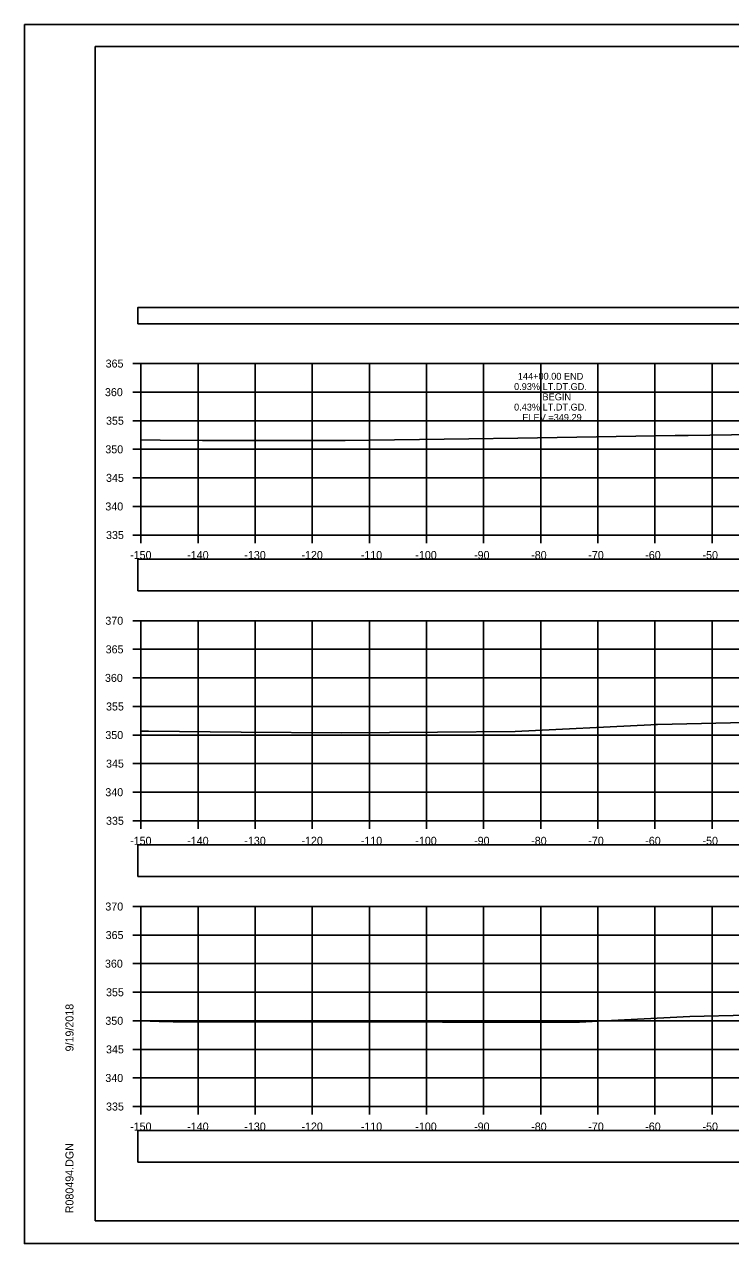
# Model space of a CAD drawing. Extents: x 1376273 to 1384221, y 378927 to 384592.
# Drawn here: x 1376887.4 to 1377011, y 382458.6 to 382671.9 of the extents above; entities that cross this region are included whole.
import ezdxf

# ---------------------------------------------------------------- set-up
doc = ezdxf.new("R2010")
doc.units = 0
for name, color, linetype in [('R_Axis', 7, 'Continuous'), ('R_Axis Annot', 7, 'Continuous'), ('R_Border', 7, 'Continuous'), ('R_Exist Surface', 7, 'Continuous'), ('R_Grid', 7, 'Continuous'), ('R_No Plot', 7, 'Continuous'), ('R_Xsect Elev', 7, 'Continuous')]:
    doc.layers.add(name, color=color, linetype=linetype)

msp = doc.modelspace()

# ---------------------------------------------------------------- linework, layer by layer
at = {"layer": 'R_Axis'}
for p, q in [((1376906.37, 382612.54), (1376907.77, 382612.54)), ((1376907.77, 382582.54), (1376907.77, 382612.54)), ((1376906.37, 382607.54), (1376907.77, 382607.54)), ((1376906.37, 382602.54), (1376907.77, 382602.54)), ((1376906.37, 382597.54), (1376907.77, 382597.54)), ((1376906.37, 382592.54), (1376907.77, 382592.54)), ((1376906.37, 382587.54), (1376907.77, 382587.54)), ((1376906.37, 382582.54), (1376907.77, 382582.54)), ((1376907.77, 382582.54), (1377207.77, 382582.54)), ((1376907.77, 382581.14), (1376907.77, 382582.54)), ((1376917.77, 382581.14), (1376917.77, 382582.54)), ((1376927.77, 382581.14), (1376927.77, 382582.54)), ((1376937.77, 382581.14), (1376937.77, 382582.54)), ((1376947.77, 382581.14), (1376947.77, 382582.54)), ((1376957.77, 382581.14), (1376957.77, 382582.54)), ((1376967.77, 382581.14), (1376967.77, 382582.54)), ((1376977.77, 382581.14), (1376977.77, 382582.54)), ((1376987.77, 382581.14), (1376987.77, 382582.54)), ((1376997.77, 382581.14), (1376997.77, 382582.54)), ((1377007.77, 382581.14), (1377007.77, 382582.54)), ((1376906.37, 382567.54), (1376907.77, 382567.54)), ((1376907.77, 382532.54), (1376907.77, 382567.54)), ((1376906.37, 382562.54), (1376907.77, 382562.54)), ((1376906.37, 382557.54), (1376907.77, 382557.54)), ((1376906.37, 382552.54), (1376907.77, 382552.54)), ((1376906.37, 382547.54), (1376907.77, 382547.54)), ((1376906.37, 382542.54), (1376907.77, 382542.54)), ((1376906.37, 382537.54), (1376907.77, 382537.54)), ((1376906.37, 382532.54), (1376907.77, 382532.54)), ((1376907.77, 382532.54), (1377207.77, 382532.54)), ((1376907.77, 382531.14), (1376907.77, 382532.54)), ((1376917.77, 382531.14), (1376917.77, 382532.54)), ((1376927.77, 382531.14), (1376927.77, 382532.54)), ((1376937.77, 382531.14), (1376937.77, 382532.54)), ((1376947.77, 382531.14), (1376947.77, 382532.54)), ((1376957.77, 382531.14), (1376957.77, 382532.54)), ((1376967.77, 382531.14), (1376967.77, 382532.54)), ((1376977.77, 382531.14), (1376977.77, 382532.54)), ((1376987.77, 382531.14), (1376987.77, 382532.54)), ((1376997.77, 382531.14), (1376997.77, 382532.54)), ((1377007.77, 382531.14), (1377007.77, 382532.54)), ((1376906.37, 382517.54), (1376907.77, 382517.54)), ((1376907.77, 382482.54), (1376907.77, 382517.54)), ((1376906.37, 382512.54), (1376907.77, 382512.54)), ((1376906.37, 382507.54), (1376907.77, 382507.54)), ((1376906.37, 382502.54), (1376907.77, 382502.54)), ((1376906.37, 382497.54), (1376907.77, 382497.54)), ((1376906.37, 382492.54), (1376907.77, 382492.54)), ((1376906.37, 382487.54), (1376907.77, 382487.54)), ((1376906.37, 382482.54), (1376907.77, 382482.54)), ((1376907.77, 382482.54), (1377207.77, 382482.54)), ((1376907.77, 382481.14), (1376907.77, 382482.54)), ((1376917.77, 382481.14), (1376917.77, 382482.54)), ((1376927.77, 382481.14), (1376927.77, 382482.54)), ((1376937.77, 382481.14), (1376937.77, 382482.54)), ((1376947.77, 382481.14), (1376947.77, 382482.54)), ((1376957.77, 382481.14), (1376957.77, 382482.54)), ((1376967.77, 382481.14), (1376967.77, 382482.54)), ((1376977.77, 382481.14), (1376977.77, 382482.54)), ((1376987.77, 382481.14), (1376987.77, 382482.54)), ((1376997.77, 382481.14), (1376997.77, 382482.54)), ((1377007.77, 382481.14), (1377007.77, 382482.54))]:
    msp.add_line(p, q, dxfattribs=at)
at = {"layer": 'R_Axis Annot'}
for points in [[(1376907.2, 382619.52), (1377209.01, 382619.52), (1377209.01, 382622.34), (1376907.2, 382622.34)], [(1376907.2, 382572.79), (1377209.01, 382572.79), (1377209.01, 382578.31), (1376907.2, 382578.31)], [(1376907.2, 382522.8), (1377209.01, 382522.8), (1377209.01, 382528.32), (1376907.2, 382528.32)], [(1376907.2, 382472.82), (1377209.01, 382472.82), (1377209.01, 382478.34), (1376907.2, 382478.34)]]:
    msp.add_lwpolyline(points, close=True, dxfattribs=at)
at = {"layer": 'R_Border'}
for p, q in [((1376899.77, 382668), (1377215.95, 382668)), ((1376899.77, 382462.54), (1376899.77, 382668)), ((1376899.77, 382462.54), (1376899.77, 382462.54)), ((1377215.95, 382462.54), (1376899.77, 382462.54))]:
    msp.add_line(p, q, dxfattribs=at)
at = {"layer": 'R_Exist Surface'}
for points in [[(1376907.77, 382599.2), (1376911.14, 382599.15), (1376918.54, 382599.1), (1376943.54, 382599.06), (1376965.19, 382599.35), (1376973.75, 382599.48), (1377001.33, 382599.96), (1377002.2, 382599.96), (1377003.6, 382599.98), (1377018.79, 382600.2)], [(1376907.77, 382548.23), (1376909.11, 382548.2), (1376925.31, 382548.07), (1376942.89, 382547.92), (1376959.72, 382548.03), (1376973.29, 382548.15), (1376997.05, 382549.34), (1376997.8, 382549.38), (1376998.24, 382549.39), (1377016.17, 382549.82)], [(1376907.77, 382497.53), (1376910.96, 382497.44), (1376913.44, 382497.34), (1376925.87, 382497.35), (1376949.75, 382497.34), (1376960.58, 382497.32), (1376984.54, 382497.3), (1376987.91, 382497.47), (1377003.86, 382498.29), (1377013.99, 382498.5)]]:
    msp.add_lwpolyline(points, dxfattribs=at)
at = {"layer": 'R_Grid'}
for p, q in [((1376907.77, 382612.54), (1377207.77, 382612.54)), ((1376907.77, 382582.54), (1376907.77, 382612.54)), ((1376907.77, 382612.54), (1377207.77, 382612.54)), ((1376907.77, 382582.54), (1376907.77, 382612.54)), ((1376917.77, 382582.54), (1376917.77, 382612.54)), ((1376917.77, 382582.54), (1376917.77, 382612.54)), ((1376927.77, 382582.54), (1376927.77, 382612.54)), ((1376927.77, 382582.54), (1376927.77, 382612.54)), ((1376937.77, 382582.54), (1376937.77, 382612.54)), ((1376937.77, 382582.54), (1376937.77, 382612.54)), ((1376947.77, 382582.54), (1376947.77, 382612.54)), ((1376947.77, 382582.54), (1376947.77, 382612.54)), ((1376957.77, 382582.54), (1376957.77, 382612.54)), ((1376957.77, 382582.54), (1376957.77, 382612.54)), ((1376967.77, 382582.54), (1376967.77, 382612.54)), ((1376967.77, 382582.54), (1376967.77, 382612.54)), ((1376977.77, 382582.54), (1376977.77, 382612.54)), ((1376977.77, 382582.54), (1376977.77, 382612.54)), ((1376987.77, 382582.54), (1376987.77, 382612.54)), ((1376987.77, 382582.54), (1376987.77, 382612.54)), ((1376997.77, 382582.54), (1376997.77, 382612.54)), ((1376997.77, 382582.54), (1376997.77, 382612.54)), ((1377007.77, 382582.54), (1377007.77, 382612.54)), ((1377007.77, 382582.54), (1377007.77, 382612.54)), ((1376907.77, 382607.54), (1377207.77, 382607.54)), ((1376907.77, 382607.54), (1377207.77, 382607.54)), ((1376907.77, 382602.54), (1377207.77, 382602.54)), ((1376907.77, 382602.54), (1377207.77, 382602.54)), ((1376907.77, 382597.54), (1377207.77, 382597.54)), ((1376907.77, 382597.54), (1377207.77, 382597.54)), ((1376907.77, 382592.54), (1377207.77, 382592.54)), ((1376907.77, 382592.54), (1377207.77, 382592.54)), ((1376907.77, 382587.54), (1377207.77, 382587.54)), ((1376907.77, 382587.54), (1377207.77, 382587.54)), ((1376907.77, 382582.54), (1377207.77, 382582.54)), ((1376907.77, 382582.54), (1377207.77, 382582.54)), ((1376907.77, 382567.54), (1377207.77, 382567.54)), ((1376907.77, 382532.54), (1376907.77, 382567.54)), ((1376907.77, 382567.54), (1377207.77, 382567.54)), ((1376907.77, 382532.54), (1376907.77, 382567.54)), ((1376917.77, 382532.54), (1376917.77, 382567.54)), ((1376917.77, 382532.54), (1376917.77, 382567.54)), ((1376927.77, 382532.54), (1376927.77, 382567.54)), ((1376927.77, 382532.54), (1376927.77, 382567.54)), ((1376937.77, 382532.54), (1376937.77, 382567.54)), ((1376937.77, 382532.54), (1376937.77, 382567.54)), ((1376947.77, 382532.54), (1376947.77, 382567.54)), ((1376947.77, 382532.54), (1376947.77, 382567.54)), ((1376957.77, 382532.54), (1376957.77, 382567.54)), ((1376957.77, 382532.54), (1376957.77, 382567.54)), ((1376967.77, 382532.54), (1376967.77, 382567.54)), ((1376967.77, 382532.54), (1376967.77, 382567.54)), ((1376977.77, 382532.54), (1376977.77, 382567.54)), ((1376977.77, 382532.54), (1376977.77, 382567.54)), ((1376987.77, 382532.54), (1376987.77, 382567.54)), ((1376987.77, 382532.54), (1376987.77, 382567.54)), ((1376997.77, 382532.54), (1376997.77, 382567.54)), ((1376997.77, 382532.54), (1376997.77, 382567.54)), ((1377007.77, 382532.54), (1377007.77, 382567.54)), ((1377007.77, 382532.54), (1377007.77, 382567.54)), ((1376907.77, 382562.54), (1377207.77, 382562.54)), ((1376907.77, 382562.54), (1377207.77, 382562.54)), ((1376907.77, 382557.54), (1377207.77, 382557.54)), ((1376907.77, 382557.54), (1377207.77, 382557.54)), ((1376907.77, 382552.54), (1377207.77, 382552.54)), ((1376907.77, 382552.54), (1377207.77, 382552.54)), ((1376907.77, 382547.54), (1377207.77, 382547.54)), ((1376907.77, 382547.54), (1377207.77, 382547.54)), ((1376907.77, 382542.54), (1377207.77, 382542.54)), ((1376907.77, 382542.54), (1377207.77, 382542.54)), ((1376907.77, 382537.54), (1377207.77, 382537.54)), ((1376907.77, 382537.54), (1377207.77, 382537.54)), ((1376907.77, 382532.54), (1377207.77, 382532.54)), ((1376907.77, 382532.54), (1377207.77, 382532.54)), ((1376907.77, 382517.54), (1377207.77, 382517.54)), ((1376907.77, 382482.54), (1376907.77, 382517.54)), ((1376907.77, 382517.54), (1377207.77, 382517.54)), ((1376907.77, 382482.54), (1376907.77, 382517.54)), ((1376917.77, 382482.54), (1376917.77, 382517.54)), ((1376917.77, 382482.54), (1376917.77, 382517.54)), ((1376927.77, 382482.54), (1376927.77, 382517.54)), ((1376927.77, 382482.54), (1376927.77, 382517.54)), ((1376937.77, 382482.54), (1376937.77, 382517.54)), ((1376937.77, 382482.54), (1376937.77, 382517.54)), ((1376947.77, 382482.54), (1376947.77, 382517.54)), ((1376947.77, 382482.54), (1376947.77, 382517.54)), ((1376957.77, 382482.54), (1376957.77, 382517.54)), ((1376957.77, 382482.54), (1376957.77, 382517.54)), ((1376967.77, 382482.54), (1376967.77, 382517.54)), ((1376967.77, 382482.54), (1376967.77, 382517.54)), ((1376977.77, 382482.54), (1376977.77, 382517.54)), ((1376977.77, 382482.54), (1376977.77, 382517.54)), ((1376987.77, 382482.54), (1376987.77, 382517.54)), ((1376987.77, 382482.54), (1376987.77, 382517.54)), ((1376997.77, 382482.54), (1376997.77, 382517.54)), ((1376997.77, 382482.54), (1376997.77, 382517.54)), ((1377007.77, 382482.54), (1377007.77, 382517.54)), ((1377007.77, 382482.54), (1377007.77, 382517.54)), ((1376907.77, 382512.54), (1377207.77, 382512.54)), ((1376907.77, 382512.54), (1377207.77, 382512.54)), ((1376907.77, 382507.54), (1377207.77, 382507.54)), ((1376907.77, 382507.54), (1377207.77, 382507.54)), ((1376907.77, 382502.54), (1377207.77, 382502.54)), ((1376907.77, 382502.54), (1377207.77, 382502.54)), ((1376907.77, 382497.54), (1377207.77, 382497.54)), ((1376907.77, 382497.54), (1377207.77, 382497.54)), ((1376907.77, 382492.54), (1377207.77, 382492.54)), ((1376907.77, 382492.54), (1377207.77, 382492.54)), ((1376907.77, 382487.54), (1377207.77, 382487.54)), ((1376907.77, 382487.54), (1377207.77, 382487.54)), ((1376907.77, 382482.54), (1377207.77, 382482.54)), ((1376907.77, 382482.54), (1377207.77, 382482.54))]:
    msp.add_line(p, q, dxfattribs=at)
at = {"layer": 'R_No Plot'}
for p, q in [((1376887.37, 382671.89), (1377220.7, 382671.89)), ((1376887.37, 382458.56), (1377220.7, 382458.56))]:
    msp.add_line(p, q, dxfattribs=at)
for points in [[(1376887.36, 382671.89), (1377220.7, 382671.89), (1377220.7, 382458.55), (1376887.36, 382458.55)], [(1377133.69, 382668), (1377133.69, 382658.12), (1377169.42, 382658.12), (1377169.42, 382655.2), (1377192.62, 382655.2), (1377192.62, 382630.86), (1377215.95, 382630.86), (1377215.95, 382462.54), (1376899.77, 382462.54), (1376899.77, 382668)]]:
    msp.add_lwpolyline(points, close=True, dxfattribs=at)

# ---------------------------------------------------------------- texts
at = {"layer": 'R_Axis Annot'}
for s, p in [('365', (1376901.59, 382611.84)), ('360', (1376901.47, 382606.84)), ('355', (1376901.66, 382601.84)), ('350', (1376901.54, 382596.84)), ('345', (1376901.66, 382591.84)), ('340', (1376901.54, 382586.84)), ('335', (1376901.66, 382581.84)), ('-150', (1376905.88, 382578.34)), ('-140', (1376915.88, 382578.34)), ('-130', (1376925.88, 382578.34)), ('-120', (1376935.88, 382578.34)), ('-110', (1376946.27, 382578.34)), ('-100', (1376955.82, 382578.34)), ('-90', (1376966.11, 382578.34)), ('-80', (1376976.11, 382578.34)), ('-70', (1376986.11, 382578.34)), ('-60', (1376996.08, 382578.34)), ('-50', (1377006.11, 382578.34)), ('370', (1376901.54, 382566.84)), ('365', (1376901.59, 382561.84)), ('360', (1376901.47, 382556.84)), ('355', (1376901.66, 382551.84)), ('350', (1376901.54, 382546.84)), ('345', (1376901.66, 382541.84)), ('340', (1376901.54, 382536.84)), ('335', (1376901.66, 382531.84)), ('-150', (1376905.88, 382528.34)), ('-140', (1376915.88, 382528.34)), ('-130', (1376925.88, 382528.34)), ('-120', (1376935.88, 382528.34)), ('-110', (1376946.27, 382528.34)), ('-100', (1376955.82, 382528.34)), ('-90', (1376966.11, 382528.34)), ('-80', (1376976.11, 382528.34)), ('-70', (1376986.11, 382528.34)), ('-60', (1376996.08, 382528.34)), ('-50', (1377006.11, 382528.34)), ('370', (1376901.54, 382516.84)), ('365', (1376901.59, 382511.84)), ('360', (1376901.47, 382506.84)), ('355', (1376901.66, 382501.84)), ('350', (1376901.54, 382496.84)), ('345', (1376901.66, 382491.84)), ('340', (1376901.54, 382486.84)), ('335', (1376901.66, 382481.84)), ('-150', (1376905.88, 382478.34)), ('-140', (1376915.88, 382478.34)), ('-130', (1376925.88, 382478.34)), ('-120', (1376935.88, 382478.34)), ('-110', (1376946.27, 382478.34)), ('-100', (1376955.82, 382478.34)), ('-90', (1376966.11, 382478.34)), ('-80', (1376976.11, 382478.34)), ('-70', (1376986.11, 382478.34)), ('-60', (1376996.08, 382478.34)), ('-50', (1377006.11, 382478.34))]:
    msp.add_text(s, height=1.4, dxfattribs=at).set_placement(p)
at = {"layer": 'R_Border'}
for s, p in [('9/19/2018', (1376895.96, 382492.18)), ('R080494.DGN', (1376895.96, 382463.86))]:
    msp.add_text(s, height=1.4, rotation=90, dxfattribs=at).set_placement(p)
at = {"layer": 'R_Xsect Elev'}
for s, p in [('144+00.00 END', (1376973.77, 382609.72)), ('0.93% LT.DT.GD.', (1376973.11, 382607.92)), ('BEGIN', (1376978.09, 382606.12)), ('0.43% LT.DT.GD.', (1376973.11, 382604.32)), ('ELEV.=349.29', (1376974.56, 382602.52))]:
    msp.add_text(s, height=1.2, rotation=360, dxfattribs=at).set_placement(p)

doc.saveas('drawing.dxf')
